(* Logix 5000 project; controller Test vendor 1 type 14 code 92 rev 33.11; software revision 33.03 *)

TASK MainTask (continuous, watchdog 500 ms) : MainProgram

MODULES
   Local : vendor 1 type 14 code 92 (ICP 0, rev 33.11)
      IN : vendor 1 type 7 code 1 (ICP 3, rev 3.2, Input RPI 20 ms)
      O : vendor 1 type 7 code 15 (ICP 2, rev 3.2, Output RPI 20 ms)
      Ethernet : 1756-ENBT (ICP 1, Ethernet 192.168.0.98, rev 6.4)
         IOLM1 : DXM (Ethernet 192.168.0.1, rev 2.22, StandardDataDriven RPI 20 ms)
              IOLM1:I.Data[184].0   // Output State
              IOLM1:I.Data[184].1   // Health Alarm State
END_MODULES

TYPE Banner_Direct_Parameters_v4 :
STRUCT
   Master_Cycle_Time : INT;
   Min_Cycle_Time : INT;
   M_Sequence_Capability : INT;
   IO_Link_Version_ID : INT;
   Process_Data_Input_Length : INT;
   Process_Data_Output_Length : INT;
   Combined_Vendor_ID : DINT;   // IO-Link Vendor ID
   Vendor_ID1 : INT;
   Vendor_ID2 : INT;
   Combined_Device_ID : DINT;   // IO-Link Device ID
   Device_ID1 : INT;
   Device_ID2 : INT;
   Device_ID3 : INT;
END_STRUCT
END_TYPE

TYPE Banner_IOL_Port_v4 :   // UDT that has all of the data items necessary to communicate with a specific Port on a IO-Link Master
STRUCT
   Port_Controlled : INT;   // Each bit represents a port on an IO-Link Master. Set to 1 to tell AOI to control that port.
   Port_Activate : INT;   // Each bit represents a port on an IO-Link Master. When ON that port will process any commands in queue.
   Port_Read : INT;   // Each bit represents a port on an IO-Link Master. Used to determine when device AOI has requested a Read command.
   Port_Write : INT;   // Each bit represents a port on an IO-Link Master. Used to determine when device AOI has requested a Write command.
   Port_RW_Complete : INT;   // Each bit represents a port on an IO-Link Master. Tells device AOI that Read or Write request has been completed.
   Port_Device_Read : INT;
   Data_Transfer : SINT[190];   // Array to transfer data from IO-Master to device AOIs.
END_STRUCT
END_TYPE

TYPE Banner_IOLM_EL_v4 :   // Error Log for Messages to IOLM.
STRUCT
   RW : SINT;   // 0 = Read, 1 = Write.
   Port : SINT;   // Port number that generated error.
   Index : INT;   // IO-Link Index for generated error.
END_STRUCT
END_TYPE

TYPE Banner_IOLM_v4 :   // UDT to control IO-Link Masters.
STRUCT
   Message_Source_Data : SINT[190];
   Message_Destination_Data : SINT[190];
   Error_Log : Banner_IOLM_EL_v4[10];
   Error_Write_Retry : BOOL;
   Num_Error_MSGS : DINT;
   IO_Link_Master_Busy : BOOL;   // 0 = While waiting for a command, 1 = Processing command
   AOI_Reset : BOOL;
   Port_Data : Banner_IOL_Port_v4;   // All of the necessary data to work with the various ports of the IO-Link Master.
   Halt_Operation : BOOL;   // When parameter is 1 the AOI is halted as next available time frame.
   AOI_Halted : BOOL;   // AOI is in standby mode until Halt Operation tag is set back to 0.
END_STRUCT
END_TYPE

TYPE Banner_S15S_TH_Alarm_Configuration_v4 :
STRUCT
   Temp_Low_Threshold : REAL;
   Temp_High_Threshold : REAL;
   Relative_Humidity_Low_Threshold : REAL;
   Relative_Humidity_High_Threshold : REAL;
   Dew_Point_Low_Threshold : REAL;
   Dew_Point_High_Threshold : REAL;
   Temp_On_Delay : REAL;
   Temp_Off_Delay : REAL;
   Relative_Humidity_On_Delay : REAL;
   Relative_Humidity_Off_Delay : REAL;
   Dew_Point_On_Delay : REAL;
   Dew_Point_Off_Delay : REAL;
END_STRUCT
END_TYPE

TYPE Banner_S15S_TH_Alarm_Counters_v4 :
STRUCT
   Temp_Low_Counter : DINT;
   Temp_High_Counter : DINT;
   Relative_Humidity_Low_Counter : DINT;
   Relative_Humidity_High_Counter : DINT;
   Dew_Point_Low_Counter : DINT;
   Dew_Point_High_Counter : DINT;
END_STRUCT
END_TYPE

TYPE Banner_S15S_TH_Floating_Point :
STRUCT
   Temp_Value : REAL;
   Temp_Over_Threshold : SINT;
   Temp_Under_Threshold : SINT;
   Dew_Point_Value : REAL;
   Dew_Point_Over_Threshold : SINT;
   Dew_Point_Under_Threshold : SINT;
   Relative_Humidity_Value : REAL;
   Relative_Humidity_Over_Threshold : SINT;
   Relative_Humidity_Under_Threshold : SINT;
END_STRUCT
END_TYPE

TYPE Banner_S15S_TH_PDI_v4 :   // Process Data for a S15S-TH-KQ. This will include event information.
STRUCT
   Smart_Fahrenheit : Banner_S15S_TH_Smart_Sensor;
   Smart_Celsius : Banner_S15S_TH_Smart_Sensor;
   Floating_Fahrenheit : Banner_S15S_TH_Floating_Point;
   Floating_Celsius : Banner_S15S_TH_Floating_Point;
   DTI : SINT[16];
END_STRUCT
END_TYPE

TYPE Banner_S15S_TH_RD_v4 :   // UDT that stores the Read Data for a S15S-TH-KQ.
STRUCT
   Direct : Banner_Direct_Parameters_v4;
   Serial_Number : STRING;
   All_Time_Run_Time : DINT;   // 0 to 2 Billion. 1/4 hr increments.
END_STRUCT
END_TYPE

TYPE Banner_S15S_TH_Smart_Sensor :
STRUCT
   Temp_Value : DINT;
   Temp_Scale : INT;
   Temp_Over_Threshold : SINT;
   Temp_Under_Threshold : SINT;
   Dew_Point_Value : DINT;
   Dew_Point_Scale : INT;
   Dew_Point_Over_Threshold : SINT;
   Dew_Point_Under_Threshold : SINT;
   Relative_Humidity_Value : DINT;
   Relative_Humidity_Scale : INT;
   Relative_Humidity_Over_Threshold : SINT;
   Relative_Humidity_Under_Threshold : SINT;
END_STRUCT
END_TYPE

TYPE Banner_S15S_TH_v4 :   // All of the parameters for a S15S-TH-KQ.
STRUCT
   Initial_Global_Read : BOOL;   // Determines if all of the IO-Link data has been read into the PLC yet
   Command : INT;   // Value placed in here will activate a read or write to a specifc IO-Link Index
   Read : Banner_S15S_TH_RD_v4;   // Read Only Data
   Write : Banner_S15S_TH_WD_v4;   // Write Data
   Reset : BOOL;   // Resets AOI. This will force a complete parameter read of the sensor.
END_STRUCT
END_TYPE

TYPE Banner_S15S_TH_WD_v4 :   // UDT that stores the Write Data for a S15S-TH-KQ.
STRUCT
   System_Command : INT;   // See IODD file for list of commands that can be activated via the System Command interface
   Parameter_Access_Lock : SINT;   // Write access to all parameters is prohibited while value is 1. Only this parameter can be adjusted when value is 1.
   Data_Storage_Lock : SINT;   // Automatic data storage is disabled when this value is equal to 1. Read access is not affected.
   Local_Parameterization_Lock : SINT;   // Parameterization via local control elements on device is disabled.
   Local_User_Interface_Lock : SINT;   // Operation of local user interface is disabled.
   Resettable_Run_Time_Counter : DINT;   // 0 to 2 Billion. 1/4 hr increments.
   Alarm_Config : Banner_S15S_TH_Alarm_Configuration_v4;
   Alarm_Counters : Banner_S15S_TH_Alarm_Counters_v4;
   Process_Data_Mode : INT;   // 1=Smart Sensor Profile, Fahrenheit, 2=Smart Sensor Profile, Celsius, 3=Floating Point, Fahrenheit, 4=Floating Point, Celsius
   Output_Config : INT;   // 0=BannerBus,1=Discrete Output
END_STRUCT
END_TYPE

ADD_ON_INSTRUCTION Banner_DXMR_IOLM_Param_v4   (* revision 4.3, vendor Banner Engineering *)
// AOI that controls a Banner IO-Link Master with Banner devices for parameter data operations.
// Revision note:
// Updated name of AOI.
VAR_IN_OUT
   IOLM : Banner_IOLM_v4; {required}
END_VAR
VAR
   Lock : DINT; {access None}
   Byte_Length : SINT; {access None}
   Current_Port : INT; {access None}   // Current port to communicate with via the IO-Link Master.
   Timer1 : TIMER := (PRE := 500); {access None}
   Error_Index : DINT; {access None}
   Timer2 : TIMER := (PRE := 5000); {access None}
   Temp_Index : INT; {access None}
   ErrCount : DINT; {access None}
   Timer4 : TIMER := (PRE := 2000); {access None}
   Timer5 : TIMER := (PRE := 2000); {access None}
   Timer3 : TIMER := (PRE := 2000); {access None}
   Timer6 : TIMER := (PRE := 3000); {access None}
   Timer7 : TIMER := (PRE := 3000); {access None}
   Timer8 : TIMER := (PRE := 3000); {access None}
END_VAR

ROUTINE Logic   (* ladder *)
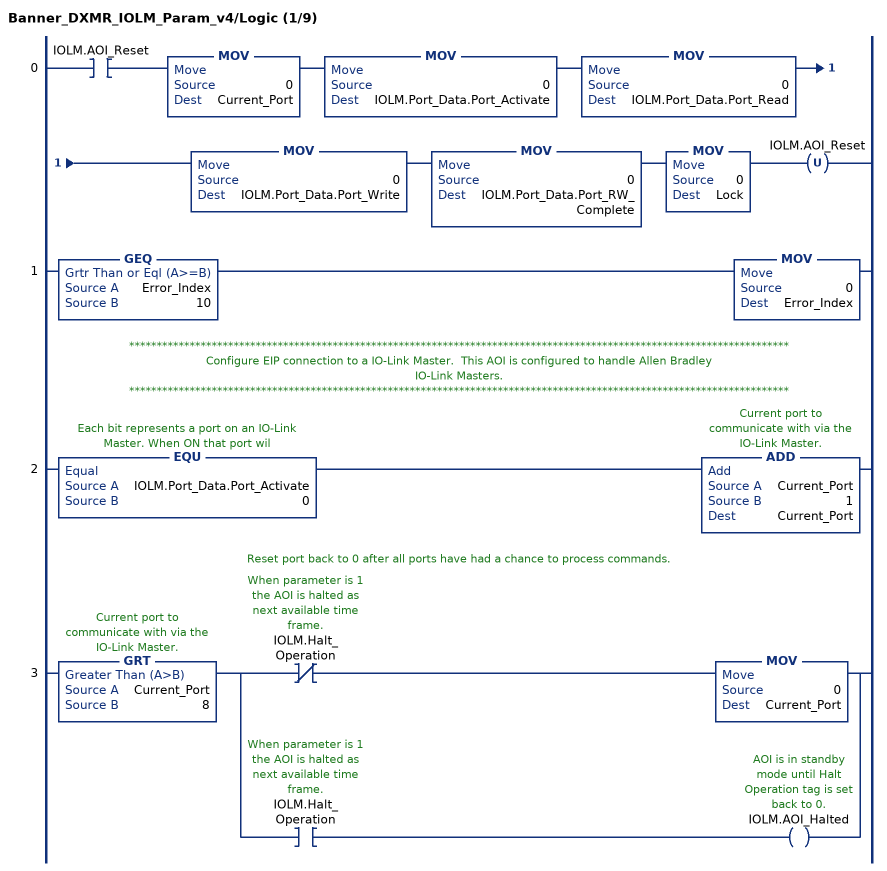
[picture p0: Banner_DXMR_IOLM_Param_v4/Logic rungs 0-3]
   0: XIC(IOLM.AOI_Reset)MOV(0,Current_Port)MOV(0,IOLM.Port_Data.Port_Activate)MOV(0,IOLM.Port_Data.Port_Read)MOV(0,IOLM.Port_Data.Port_Write)MOV(0,IOLM.Port_Data.Port_RW_Complete)MOV(0,Lock)OTU(IOLM.AOI_Reset);
   1: GEQ(Error_Index,10)MOV(0,Error_Index);
   // ************************************************************************************************************************
   // Configure EIP connection to a IO-Link Master.  This AOI is configured to handle Allen Bradley
   // IO-Link Masters.
   // ************************************************************************************************************************
   2: EQU(IOLM.Port_Data.Port_Activate,0)ADD(Current_Port,1,Current_Port);
   // Reset port back to 0 after all ports have had a chance to process commands.
   3: GRT(Current_Port,8)[XIO(IOLM.Halt_Operation) MOV(0,Current_Port) ,XIC(IOLM.Halt_Operation) OTE(IOLM.AOI_Halted) ];
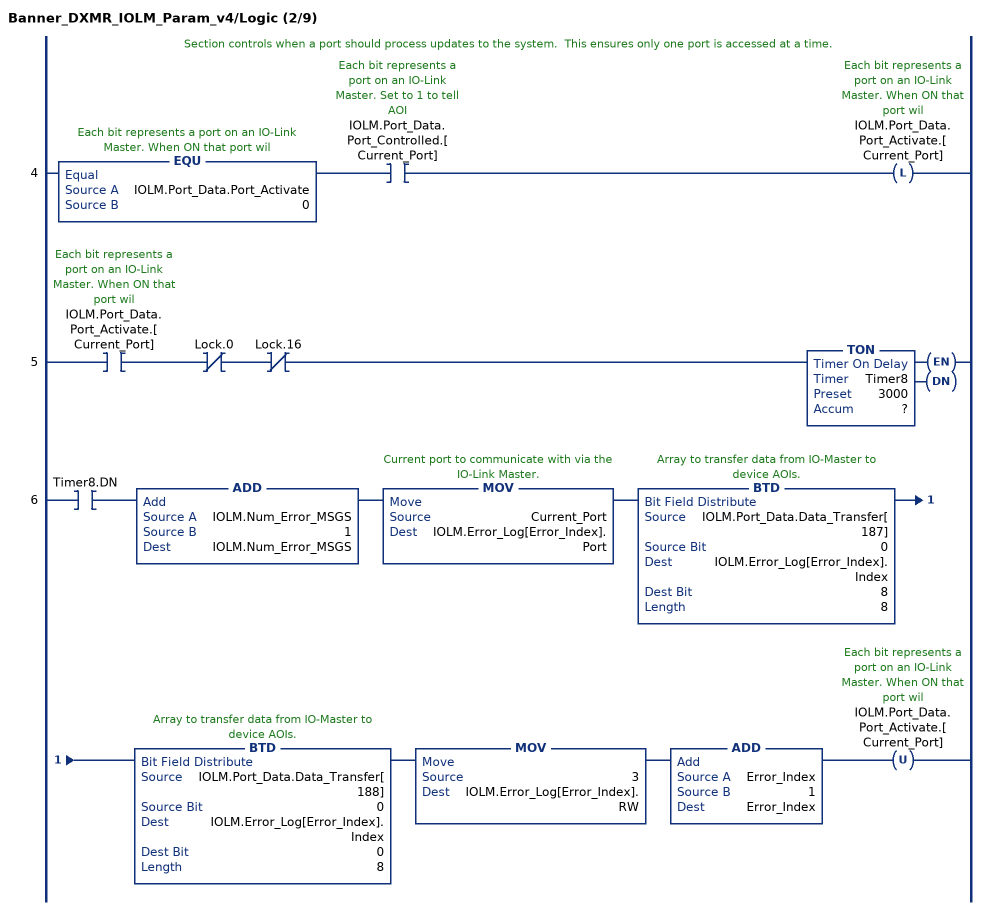
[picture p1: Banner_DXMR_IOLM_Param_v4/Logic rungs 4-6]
   // Section controls when a port should process updates to the system.  This ensures only one port is accessed at a time.
   4: EQU(IOLM.Port_Data.Port_Activate,0)XIC(IOLM.Port_Data.Port_Controlled.[Current_Port])OTL(IOLM.Port_Data.Port_Activate.[Current_Port]);
   5: XIC(IOLM.Port_Data.Port_Activate.[Current_Port])XIO(Lock.0)XIO(Lock.16)TON(Timer8,?,?);
   6: XIC(Timer8.DN)ADD(IOLM.Num_Error_MSGS,1,IOLM.Num_Error_MSGS)MOV(Current_Port,IOLM.Error_Log[Error_Index].Port)BTD(IOLM.Port_Data.Data_Transfer[187],0,IOLM.Error_Log[Error_Index].Index,8,8)BTD(IOLM.Port_Data.Data_Transfer[188],0,IOLM.Error_Log[Error_Index].Index,0,8)MOV(3,IOLM.Error_Log[Error_Index].RW)ADD(Error_Index,1,Error_Index)OTU(IOLM.Port_Data.Port_Activate.[Current_Port]);
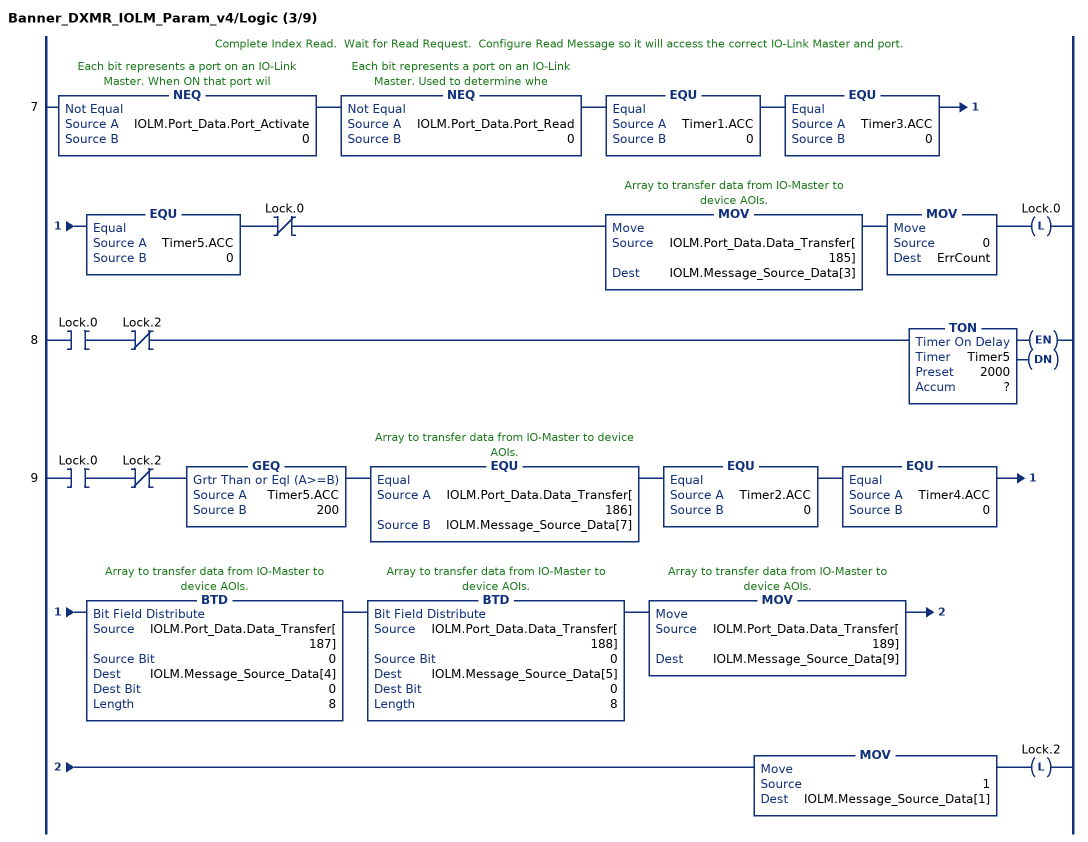
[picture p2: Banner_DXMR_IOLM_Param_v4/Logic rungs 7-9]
   // Complete Index Read.  Wait for Read Request.  Configure Read Message so it will access the correct IO-Link Master and port.
   7: NEQ(IOLM.Port_Data.Port_Activate,0)NEQ(IOLM.Port_Data.Port_Read,0)EQU(Timer1.ACC,0)EQU(Timer3.ACC,0)EQU(Timer5.ACC,0)XIO(Lock.0)MOV(IOLM.Port_Data.Data_Transfer[185],IOLM.Message_Source_Data[3])MOV(0,ErrCount)OTL(Lock.0);
   8: XIC(Lock.0)XIO(Lock.2)TON(Timer5,?,?);
   9: XIC(Lock.0)XIO(Lock.2)GEQ(Timer5.ACC,200)EQU(IOLM.Port_Data.Data_Transfer[186],IOLM.Message_Source_Data[7])EQU(Timer2.ACC,0)EQU(Timer4.ACC,0)BTD(IOLM.Port_Data.Data_Transfer[187],0,IOLM.Message_Source_Data[4],0,8)BTD(IOLM.Port_Data.Data_Transfer[188],0,IOLM.Message_Source_Data[5],0,8)MOV(IOLM.Port_Data.Data_Transfer[189],IOLM.Message_Source_Data[9])MOV(1,IOLM.Message_Source_Data[1])OTL(Lock.2);
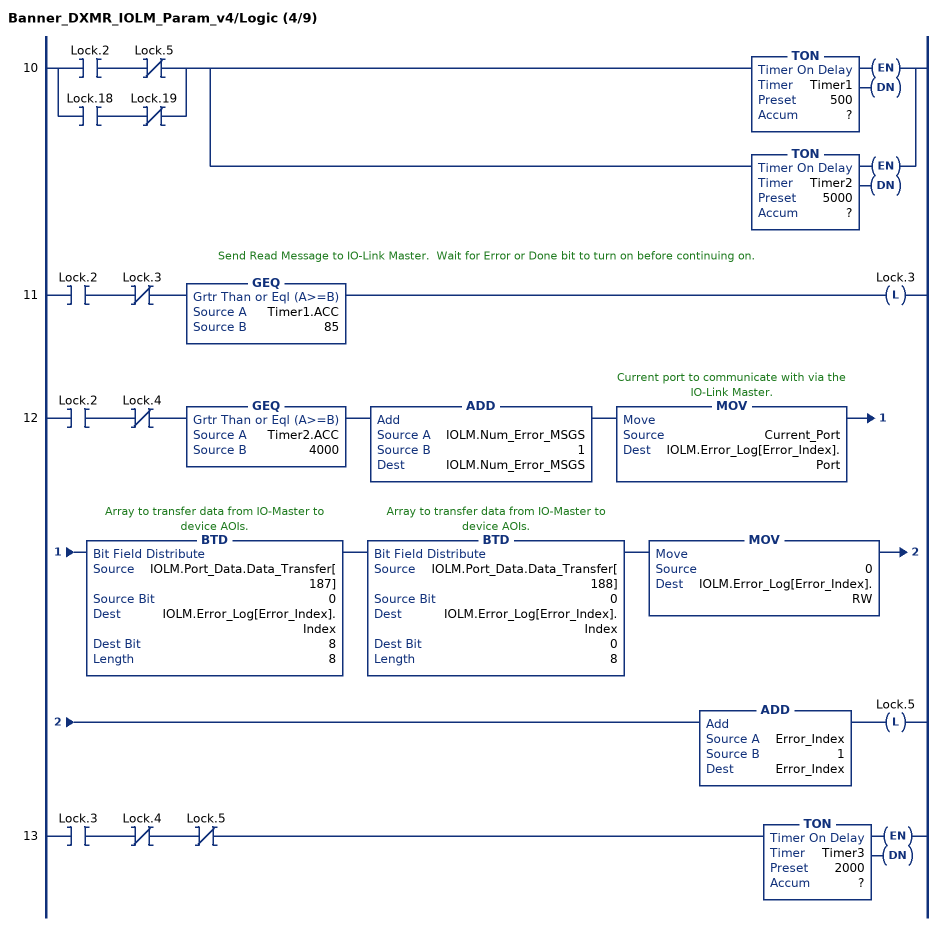
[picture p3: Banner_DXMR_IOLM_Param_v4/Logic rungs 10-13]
   10: [XIC(Lock.2) XIO(Lock.5) ,XIC(Lock.18) XIO(Lock.19) ][TON(Timer1,?,?) ,TON(Timer2,?,?) ];
   // Send Read Message to IO-Link Master.  Wait for Error or Done bit to turn on before continuing on.
   11: XIC(Lock.2)XIO(Lock.3)GEQ(Timer1.ACC,85)OTL(Lock.3);
   12: XIC(Lock.2)XIO(Lock.4)GEQ(Timer2.ACC,4000)ADD(IOLM.Num_Error_MSGS,1,IOLM.Num_Error_MSGS)MOV(Current_Port,IOLM.Error_Log[Error_Index].Port)BTD(IOLM.Port_Data.Data_Transfer[187],0,IOLM.Error_Log[Error_Index].Index,8,8)BTD(IOLM.Port_Data.Data_Transfer[188],0,IOLM.Error_Log[Error_Index].Index,0,8)MOV(0,IOLM.Error_Log[Error_Index].RW)ADD(Error_Index,1,Error_Index)OTL(Lock.5);
   13: XIC(Lock.3)XIO(Lock.4)XIO(Lock.5)TON(Timer3,?,?);
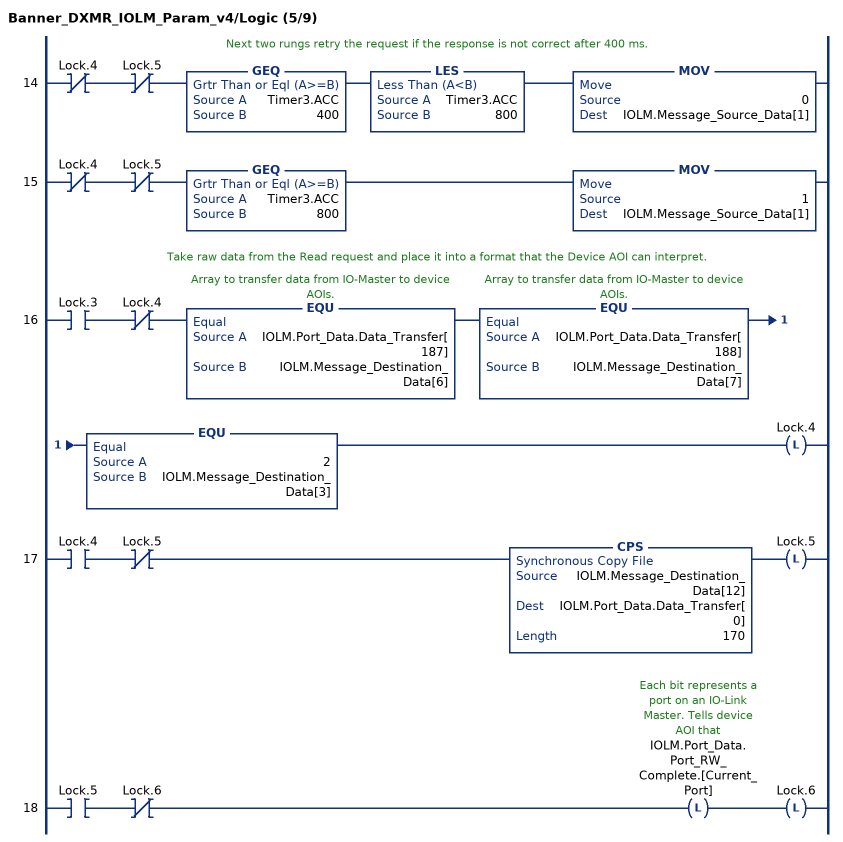
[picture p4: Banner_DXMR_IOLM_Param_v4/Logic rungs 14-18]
   // Next two rungs retry the request if the response is not correct after 400 ms.
   14: XIO(Lock.4)XIO(Lock.5)GEQ(Timer3.ACC,400)LES(Timer3.ACC,800)MOV(0,IOLM.Message_Source_Data[1]);
   15: XIO(Lock.4)XIO(Lock.5)GEQ(Timer3.ACC,800)MOV(1,IOLM.Message_Source_Data[1]);
   // Take raw data from the Read request and place it into a format that the Device AOI can interpret.
   16: XIC(Lock.3)XIO(Lock.4)EQU(IOLM.Port_Data.Data_Transfer[187],IOLM.Message_Destination_Data[6])EQU(IOLM.Port_Data.Data_Transfer[188],IOLM.Message_Destination_Data[7])EQU(2,IOLM.Message_Destination_Data[3])OTL(Lock.4);
   17: XIC(Lock.4)XIO(Lock.5)CPS(IOLM.Message_Destination_Data[12],IOLM.Port_Data.Data_Transfer[0],170)OTL(Lock.5);
   18: XIC(Lock.5)XIO(Lock.6)OTL(IOLM.Port_Data.Port_RW_Complete.[Current_Port])OTL(Lock.6);
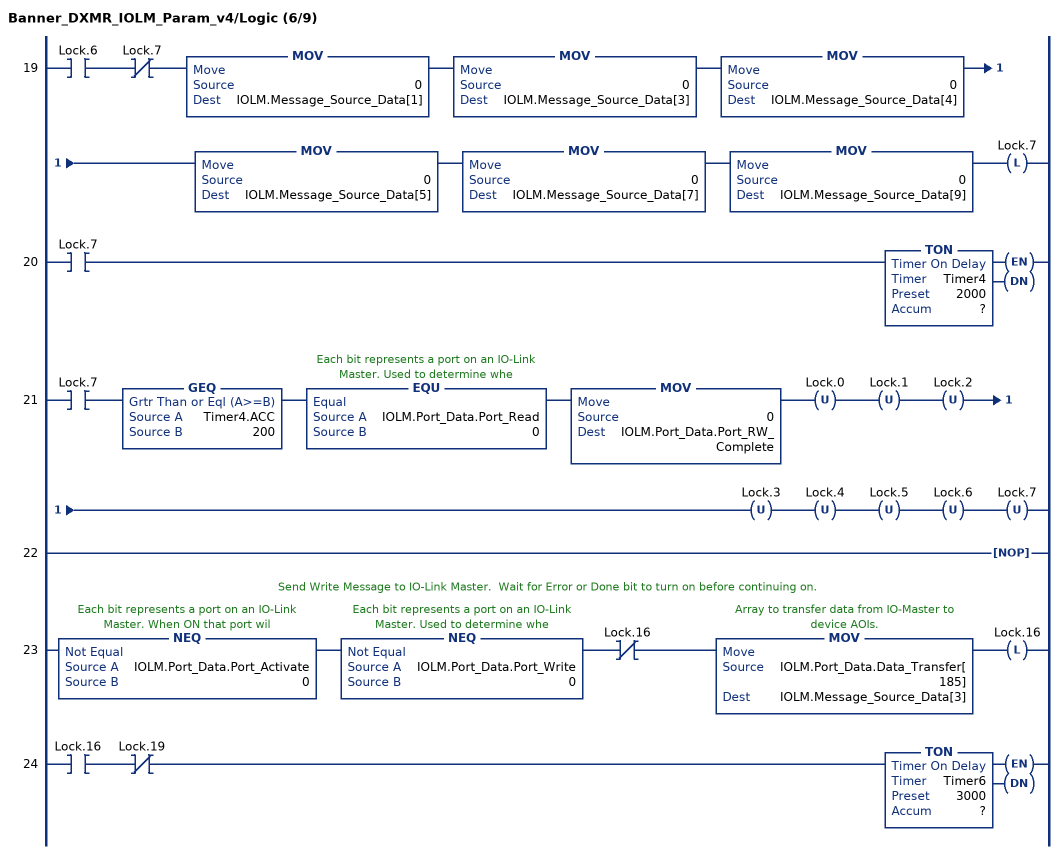
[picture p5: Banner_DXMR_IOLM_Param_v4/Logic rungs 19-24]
   19: XIC(Lock.6)XIO(Lock.7)MOV(0,IOLM.Message_Source_Data[1])MOV(0,IOLM.Message_Source_Data[3])MOV(0,IOLM.Message_Source_Data[4])MOV(0,IOLM.Message_Source_Data[5])MOV(0,IOLM.Message_Source_Data[7])MOV(0,IOLM.Message_Source_Data[9])OTL(Lock.7);
   20: XIC(Lock.7)TON(Timer4,?,?);
   21: XIC(Lock.7)GEQ(Timer4.ACC,200)EQU(IOLM.Port_Data.Port_Read,0)MOV(0,IOLM.Port_Data.Port_RW_Complete)OTU(Lock.0)OTU(Lock.1)OTU(Lock.2)OTU(Lock.3)OTU(Lock.4)OTU(Lock.5)OTU(Lock.6)OTU(Lock.7);
   22: NOP();
   // Send Write Message to IO-Link Master.  Wait for Error or Done bit to turn on before continuing on.
   23: NEQ(IOLM.Port_Data.Port_Activate,0)NEQ(IOLM.Port_Data.Port_Write,0)XIO(Lock.16)MOV(IOLM.Port_Data.Data_Transfer[185],IOLM.Message_Source_Data[3])OTL(Lock.16);
   24: XIC(Lock.16)XIO(Lock.19)TON(Timer6,?,?);
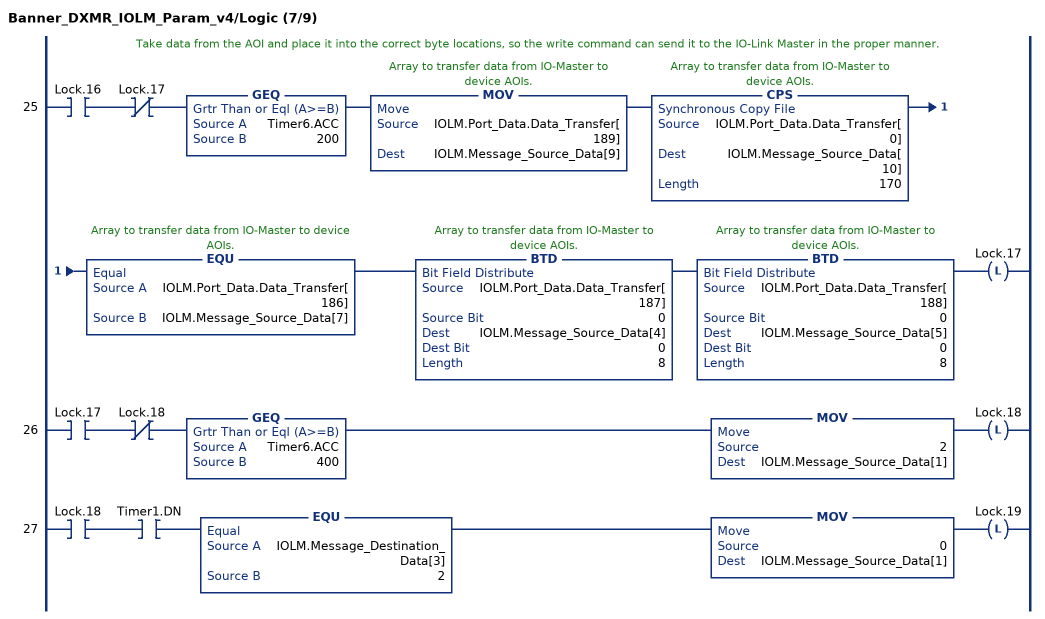
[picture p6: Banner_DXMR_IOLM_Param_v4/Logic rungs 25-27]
   // Take data from the AOI and place it into the correct byte locations, so the write command can send it to the IO-Link Master in the proper manner.
   25: XIC(Lock.16)XIO(Lock.17)GEQ(Timer6.ACC,200)MOV(IOLM.Port_Data.Data_Transfer[189],IOLM.Message_Source_Data[9])CPS(IOLM.Port_Data.Data_Transfer[0],IOLM.Message_Source_Data[10],170)EQU(IOLM.Port_Data.Data_Transfer[186],IOLM.Message_Source_Data[7])BTD(IOLM.Port_Data.Data_Transfer[187],0,IOLM.Message_Source_Data[4],0,8)BTD(IOLM.Port_Data.Data_Transfer[188],0,IOLM.Message_Source_Data[5],0,8)OTL(Lock.17);
   26: XIC(Lock.17)XIO(Lock.18)GEQ(Timer6.ACC,400)MOV(2,IOLM.Message_Source_Data[1])OTL(Lock.18);
   27: XIC(Lock.18)XIC(Timer1.DN)EQU(IOLM.Message_Destination_Data[3],2)MOV(0,IOLM.Message_Source_Data[1])OTL(Lock.19);
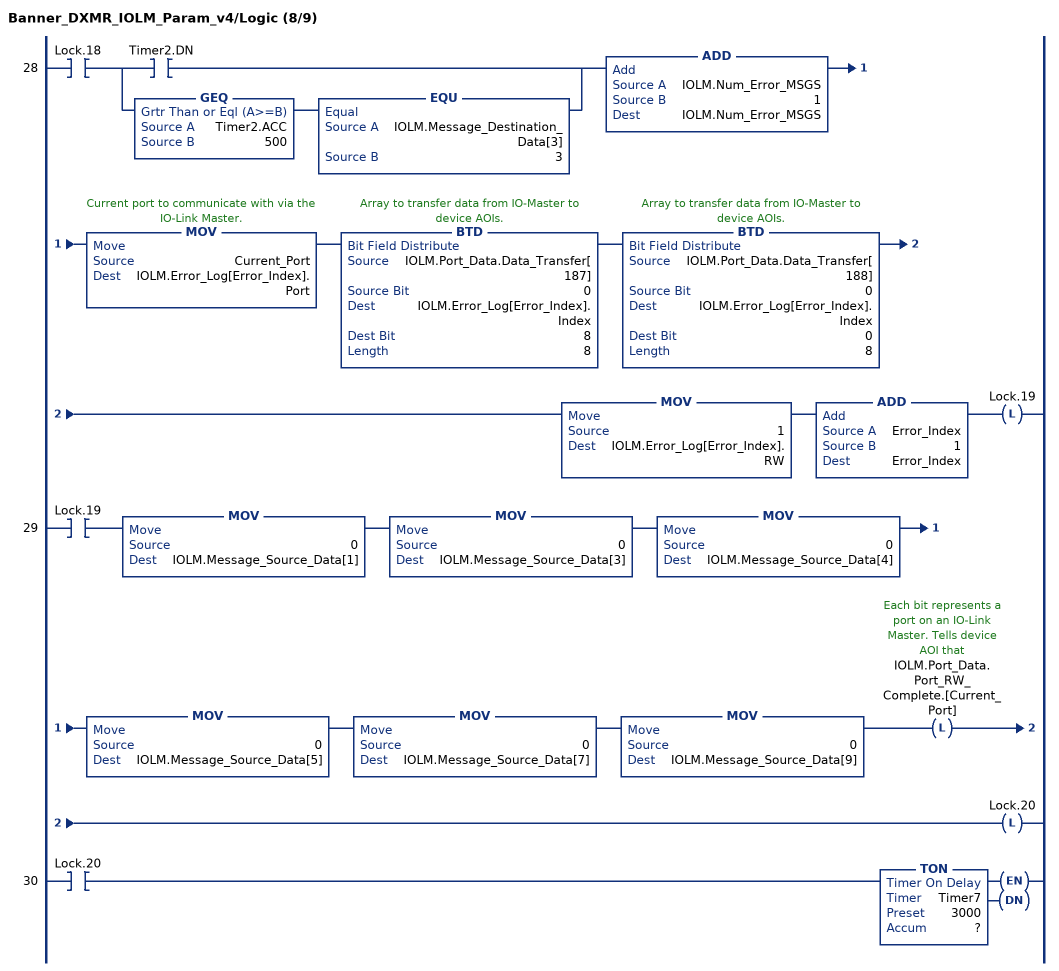
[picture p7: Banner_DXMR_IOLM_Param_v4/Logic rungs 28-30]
   28: XIC(Lock.18)[XIC(Timer2.DN) ,GEQ(Timer2.ACC,500) EQU(IOLM.Message_Destination_Data[3],3) ]ADD(IOLM.Num_Error_MSGS,1,IOLM.Num_Error_MSGS)MOV(Current_Port,IOLM.Error_Log[Error_Index].Port)BTD(IOLM.Port_Data.Data_Transfer[187],0,IOLM.Error_Log[Error_Index].Index,8,8)BTD(IOLM.Port_Data.Data_Transfer[188],0,IOLM.Error_Log[Error_Index].Index,0,8)MOV(1,IOLM.Error_Log[Error_Index].RW)ADD(Error_Index,1,Error_Index)OTL(Lock.19);
   29: XIC(Lock.19)MOV(0,IOLM.Message_Source_Data[1])MOV(0,IOLM.Message_Source_Data[3])MOV(0,IOLM.Message_Source_Data[4])MOV(0,IOLM.Message_Source_Data[5])MOV(0,IOLM.Message_Source_Data[7])MOV(0,IOLM.Message_Source_Data[9])OTL(IOLM.Port_Data.Port_RW_Complete.[Current_Port])OTL(Lock.20);
   30: XIC(Lock.20)TON(Timer7,?,?);
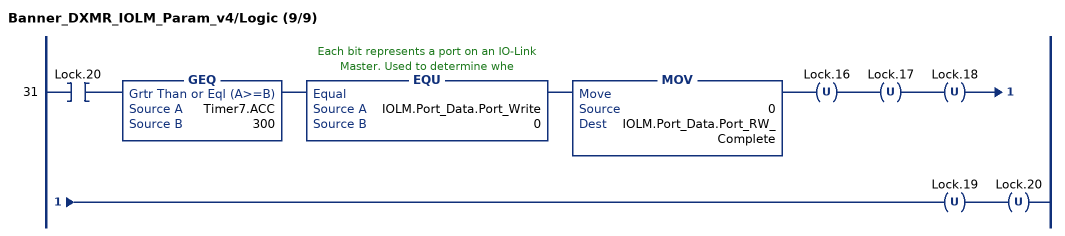
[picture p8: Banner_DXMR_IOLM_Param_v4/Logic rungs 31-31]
   31: XIC(Lock.20)GEQ(Timer7.ACC,300)EQU(IOLM.Port_Data.Port_Write,0)MOV(0,IOLM.Port_Data.Port_RW_Complete)OTU(Lock.16)OTU(Lock.17)OTU(Lock.18)OTU(Lock.19)OTU(Lock.20);
END_ROUTINE
END_ADD_ON_INSTRUCTION

ADD_ON_INSTRUCTION Banner_S15S_TH_Float_In_v4   (* revision 4.0 *)
// AOI the orientates the bytes for a floating point value.
VAR_IN_OUT
   Float : REAL; {required}
END_VAR
VAR_INPUT
   Sint0 : SINT; {required}
   Sint1 : SINT; {required}
   Sint2 : SINT; {required}
   Sint3 : SINT; {required}
END_VAR
VAR
   Temp_Byte : SINT[4]; {access None}
END_VAR

ROUTINE Logic   (* ladder *)
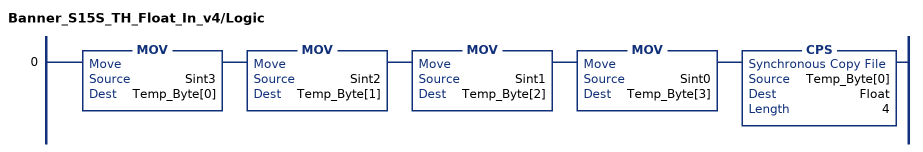
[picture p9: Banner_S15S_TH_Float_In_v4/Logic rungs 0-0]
   0: MOV(Sint3,Temp_Byte[0])MOV(Sint2,Temp_Byte[1])MOV(Sint1,Temp_Byte[2])MOV(Sint0,Temp_Byte[3])CPS(Temp_Byte[0],Float,4);
END_ROUTINE
END_ADD_ON_INSTRUCTION

ADD_ON_INSTRUCTION Banner_S15S_TH_Float_Out_v4   (* revision 4.0 *)
// AOI the orientates the bytes for a floating point value.
VAR_INPUT
   Float : REAL; {required}
END_VAR
VAR_IN_OUT
   Sint0 : SINT; {required}
   Sint1 : SINT; {required}
   Sint2 : SINT; {required}
   Sint3 : SINT; {required}
END_VAR
VAR
   Temp_Byte : SINT[4]; {access None}
END_VAR

ROUTINE Logic   (* ladder *)
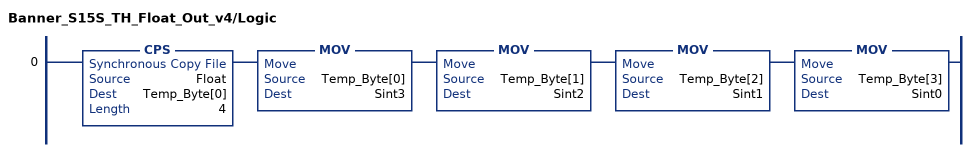
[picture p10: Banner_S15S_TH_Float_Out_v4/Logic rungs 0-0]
   0: CPS(Float,Temp_Byte[0],4)MOV(Temp_Byte[0],Sint3)MOV(Temp_Byte[1],Sint2)MOV(Temp_Byte[2],Sint1)MOV(Temp_Byte[3],Sint0);
END_ROUTINE
END_ADD_ON_INSTRUCTION

ADD_ON_INSTRUCTION Banner_S15S_TH_Param_v4   (* revision 4.0, vendor Banner Engineering *)
// AOI to read and write parameter data to an IO-Link S15S-TH-KQ.
VAR_IN_OUT
   S15STH : Banner_S15S_TH_v4; {required}
   Port_Data : Banner_IOL_Port_v4; {required}
END_VAR
VAR_INPUT
   Port : DINT; {required}
END_VAR
VAR
   Local_Control : DINT; {access None}
   Global_Read_Command_Value : INT; {access None}
   Global_Write_Command_Value : INT; {access None}
   Command_Being_Processed : BOOL; {access None}
   Update_Archive : BOOL; {access None}
   Index_Write_Inprocess : INT; {access None}
   Index_Write_Control : INT; {access None}
   Inprocess_Index : DINT; {access None}
   AOI_Out_Status : Banner_S15S_TH_Float_Out_v4[12]; {access None}
   AOI_In_Status : Banner_S15S_TH_Float_In_v4[12]; {access None}
END_VAR

ROUTINE Logic   (* ladder *)
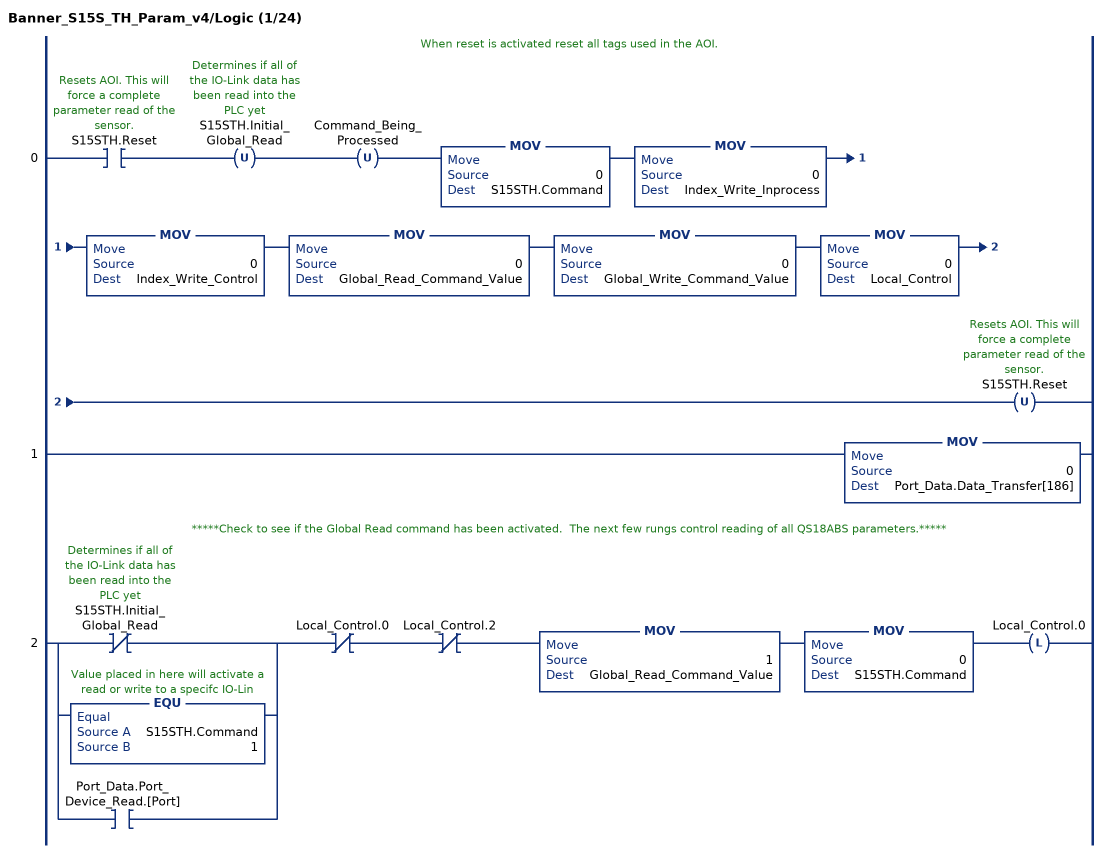
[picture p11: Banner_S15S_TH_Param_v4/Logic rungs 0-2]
   // When reset is activated reset all tags used in the AOI.
   0: XIC(S15STH.Reset)OTU(S15STH.Initial_Global_Read)OTU(Command_Being_Processed)MOV(0,S15STH.Command)MOV(0,Index_Write_Inprocess)MOV(0,Index_Write_Control)MOV(0,Global_Read_Command_Value)MOV(0,Global_Write_Command_Value)MOV(0,Local_Control)OTU(S15STH.Reset);
   1: MOV(0,Port_Data.Data_Transfer[186]);
   // *****Check to see if the Global Read command has been activated.  The next few rungs control reading of all QS18ABS parameters.*****
   2: [XIO(S15STH.Initial_Global_Read) ,EQU(S15STH.Command,1) ,XIC(Port_Data.Port_Device_Read.[Port]) ]XIO(Local_Control.0)XIO(Local_Control.2)MOV(1,Global_Read_Command_Value)MOV(0,S15STH.Command)OTL(Local_Control.0);
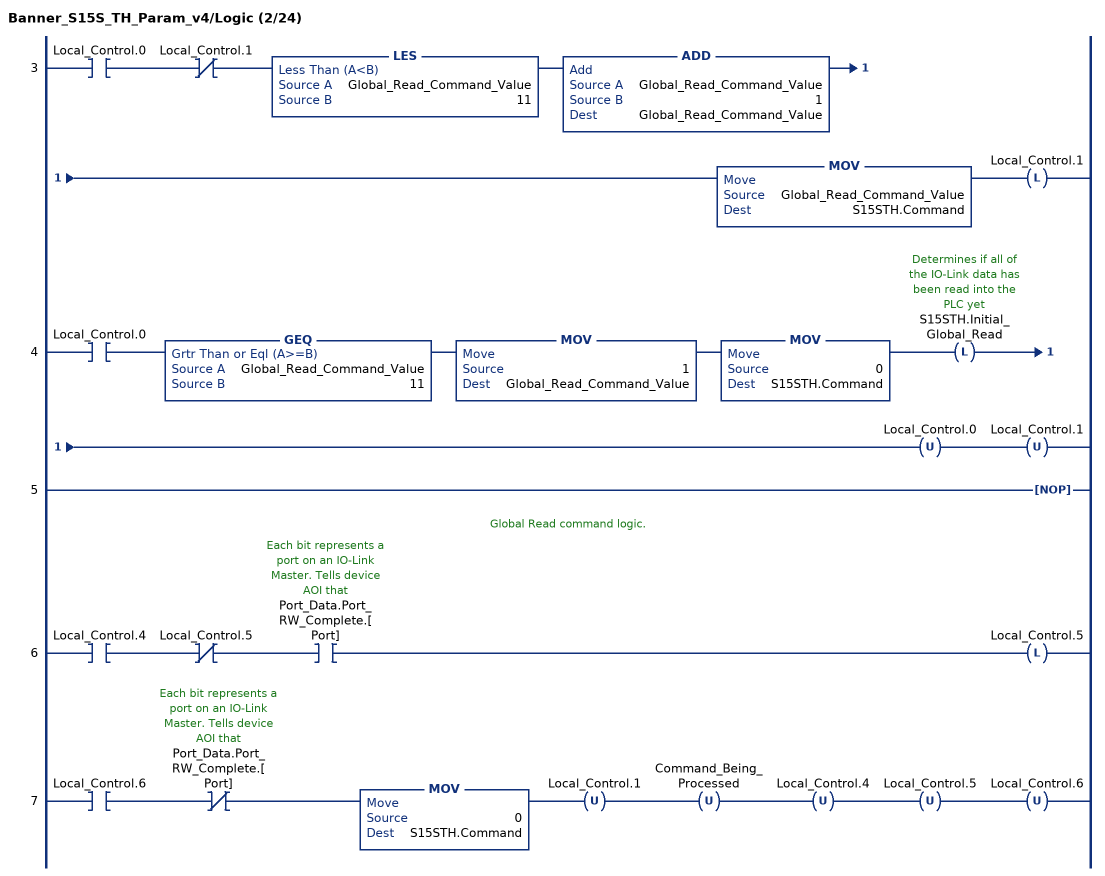
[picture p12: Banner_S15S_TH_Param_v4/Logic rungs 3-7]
   3: XIC(Local_Control.0)XIO(Local_Control.1)LES(Global_Read_Command_Value,11)ADD(Global_Read_Command_Value,1,Global_Read_Command_Value)MOV(Global_Read_Command_Value,S15STH.Command)OTL(Local_Control.1);
   4: XIC(Local_Control.0)GEQ(Global_Read_Command_Value,11)MOV(1,Global_Read_Command_Value)MOV(0,S15STH.Command)OTL(S15STH.Initial_Global_Read)OTU(Local_Control.0)OTU(Local_Control.1);
   5: NOP();
   // Global Read command logic.
   6: XIC(Local_Control.4)XIO(Local_Control.5)XIC(Port_Data.Port_RW_Complete.[Port])OTL(Local_Control.5);
   7: XIC(Local_Control.6)XIO(Port_Data.Port_RW_Complete.[Port])MOV(0,S15STH.Command)OTU(Local_Control.1)OTU(Command_Being_Processed)OTU(Local_Control.4)OTU(Local_Control.5)OTU(Local_Control.6);
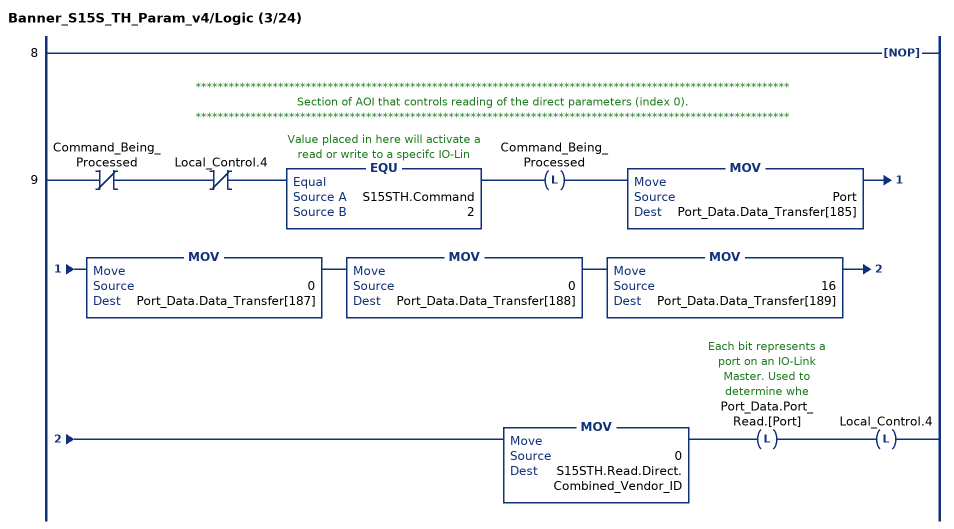
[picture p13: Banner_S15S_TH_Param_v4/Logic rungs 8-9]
   8: NOP();
   // ************************************************************************************************************
   // Section of AOI that controls reading of the direct parameters (index 0).
   // ************************************************************************************************************
   9: XIO(Command_Being_Processed)XIO(Local_Control.4)EQU(S15STH.Command,2)OTL(Command_Being_Processed)MOV(Port,Port_Data.Data_Transfer[185])MOV(0,Port_Data.Data_Transfer[187])MOV(0,Port_Data.Data_Transfer[188])MOV(16,Port_Data.Data_Transfer[189])MOV(0,S15STH.Read.Direct.Combined_Vendor_ID)OTL(Port_Data.Port_Read.[Port])OTL(Local_Control.4);
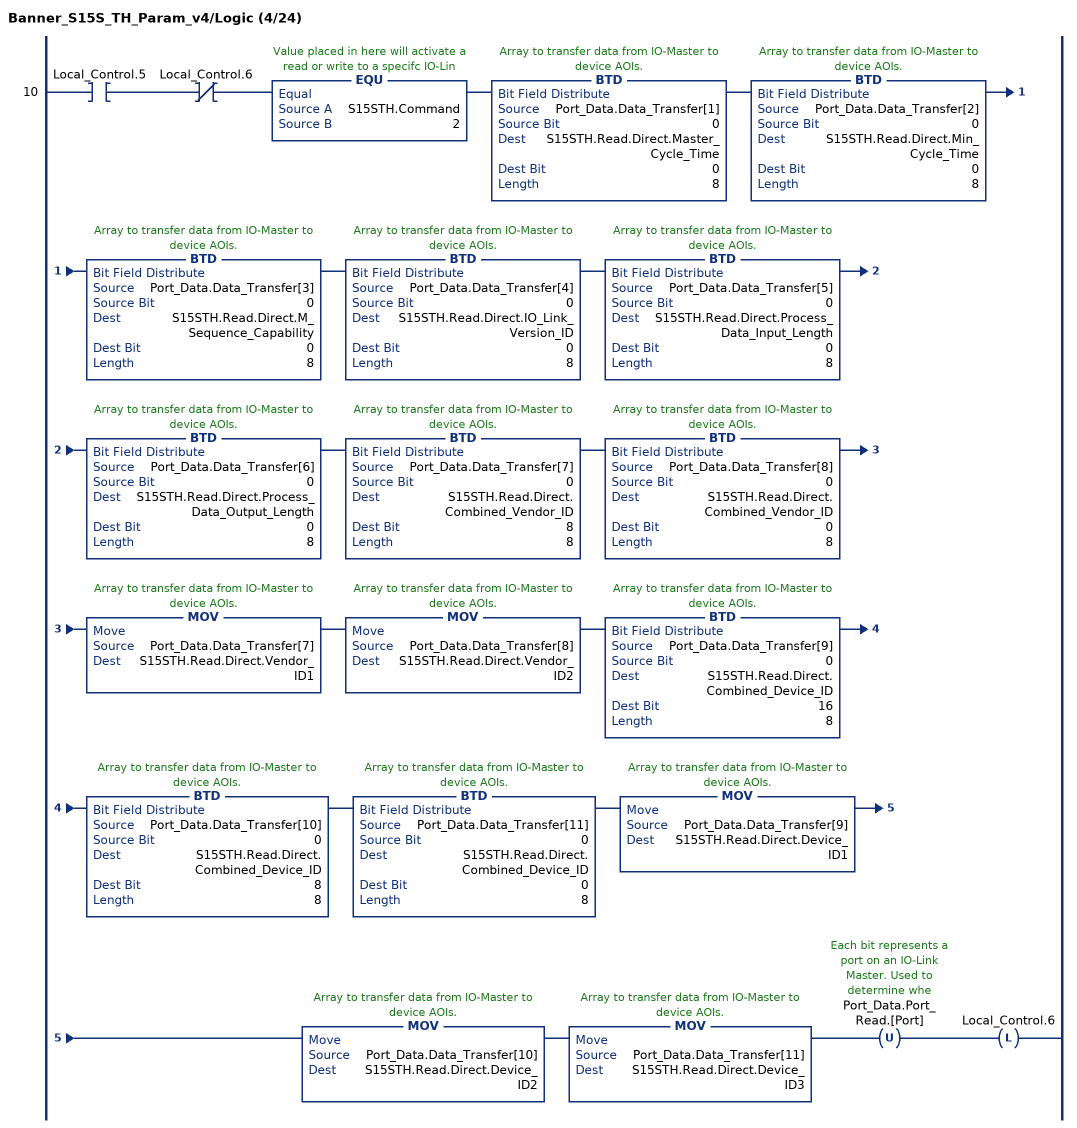
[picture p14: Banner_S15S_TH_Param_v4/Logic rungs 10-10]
   10: XIC(Local_Control.5)XIO(Local_Control.6)EQU(S15STH.Command,2)BTD(Port_Data.Data_Transfer[1],0,S15STH.Read.Direct.Master_Cycle_Time,0,8)BTD(Port_Data.Data_Transfer[2],0,S15STH.Read.Direct.Min_Cycle_Time,0,8)BTD(Port_Data.Data_Transfer[3],0,S15STH.Read.Direct.M_Sequence_Capability,0,8)BTD(Port_Data.Data_Transfer[4],0,S15STH.Read.Direct.IO_Link_Version_ID,0,8)BTD(Port_Data.Data_Transfer[5],0,S15STH.Read.Direct.Process_Data_Input_Length,0,8)BTD(Port_Data.Data_Transfer[6],0,S15STH.Read.Direct.Process_Data_Output_Length,0,8)BTD(Port_Data.Data_Transfer[7],0,S15STH.Read.Direct.Combined_Vendor_ID,8,8)BTD(Port_Data.Data_Transfer[8],0,S15STH.Read.Direct.Combined_Vendor_ID,0,8)MOV(Port_Data.Data_Transfer[7],S15STH.Read.Direct.Vendor_ID1)MOV(Port_Data.Data_Transfer[8],S15STH.Read.Direct.Vendor_ID2)BTD(Port_Data.Data_Transfer[9],0,S15STH.Read.Direct.Combined_Device_ID,16,8)BTD(Port_Data.Data_Transfer[10],0,S15STH.Read.Direct.Combined_Device_ID,8,8)BTD(Port_Data.Data_Transfer[11],0,S15STH.Read.Direct.Combined_Device_ID,0,8)MOV(Port_Data.Data_Transfer[9],S15STH.Read.Direct.Device_ID1)MOV(Port_Data.Data_Transfer[10],S15STH.Read.Direct.Device_ID2)MOV(Port_Data.Data_Transfer[11],S15STH.Read.Direct.Device_ID3)OTU(Port_Data.Port_Read.[Port])OTL(Local_Control.6);
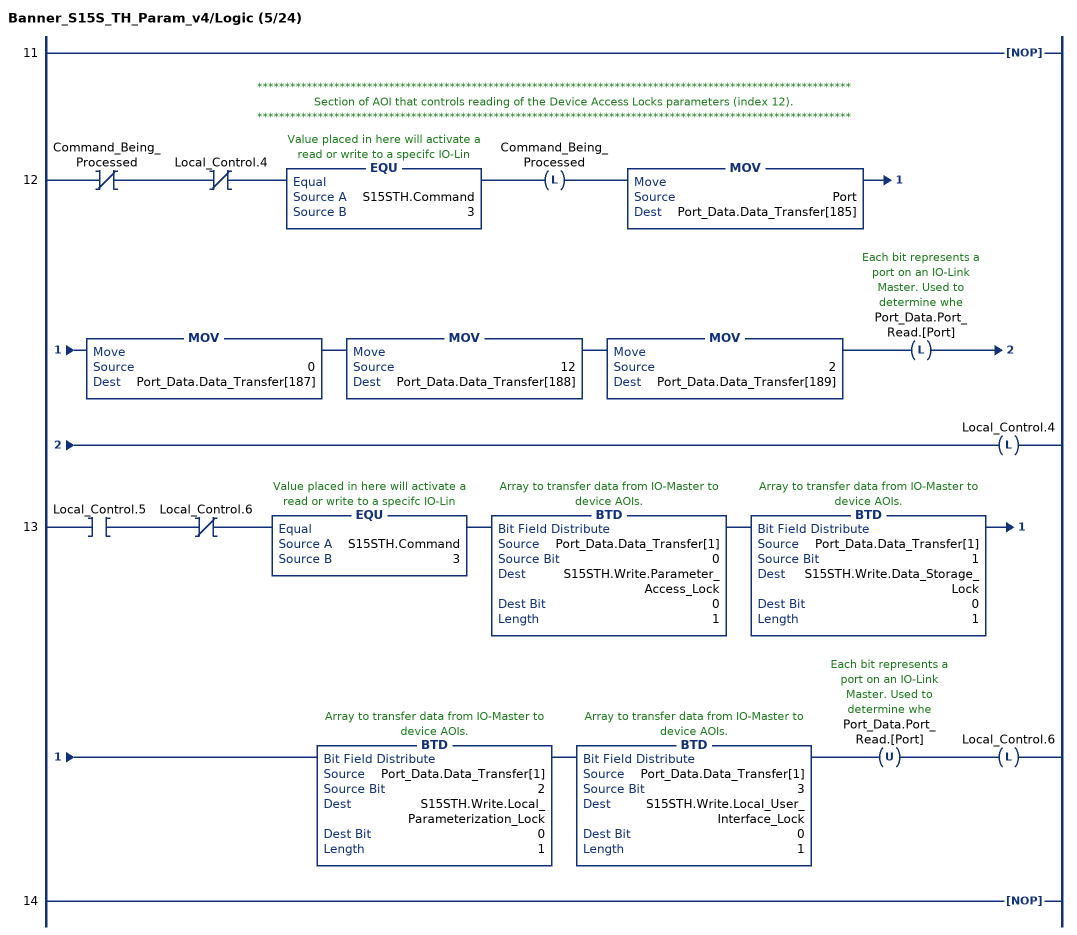
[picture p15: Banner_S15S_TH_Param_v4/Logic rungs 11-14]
   11: NOP();
   // ************************************************************************************************************
   // Section of AOI that controls reading of the Device Access Locks parameters (index 12).
   // ************************************************************************************************************
   12: XIO(Command_Being_Processed)XIO(Local_Control.4)EQU(S15STH.Command,3)OTL(Command_Being_Processed)MOV(Port,Port_Data.Data_Transfer[185])MOV(0,Port_Data.Data_Transfer[187])MOV(12,Port_Data.Data_Transfer[188])MOV(2,Port_Data.Data_Transfer[189])OTL(Port_Data.Port_Read.[Port])OTL(Local_Control.4);
   13: XIC(Local_Control.5)XIO(Local_Control.6)EQU(S15STH.Command,3)BTD(Port_Data.Data_Transfer[1],0,S15STH.Write.Parameter_Access_Lock,0,1)BTD(Port_Data.Data_Transfer[1],1,S15STH.Write.Data_Storage_Lock,0,1)BTD(Port_Data.Data_Transfer[1],2,S15STH.Write.Local_Parameterization_Lock,0,1)BTD(Port_Data.Data_Transfer[1],3,S15STH.Write.Local_User_Interface_Lock,0,1)OTU(Port_Data.Port_Read.[Port])OTL(Local_Control.6);
   14: NOP();
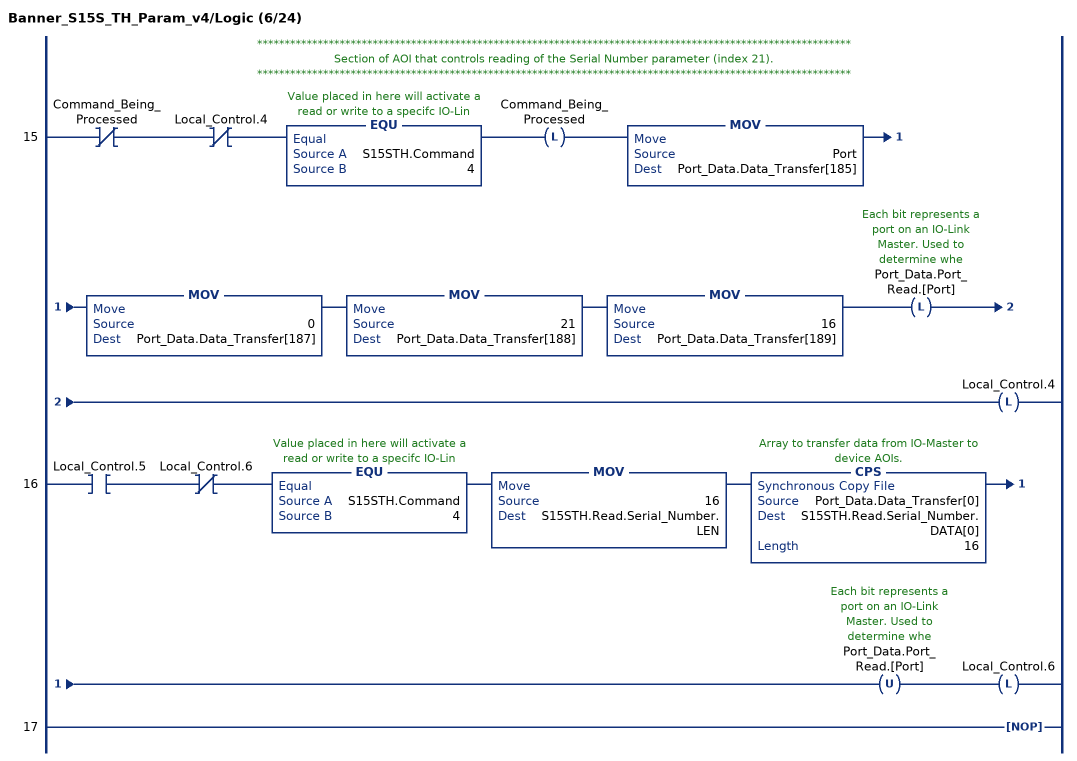
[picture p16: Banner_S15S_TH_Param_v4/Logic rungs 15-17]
   // ************************************************************************************************************
   // Section of AOI that controls reading of the Serial Number parameter (index 21).
   // ************************************************************************************************************
   15: XIO(Command_Being_Processed)XIO(Local_Control.4)EQU(S15STH.Command,4)OTL(Command_Being_Processed)MOV(Port,Port_Data.Data_Transfer[185])MOV(0,Port_Data.Data_Transfer[187])MOV(21,Port_Data.Data_Transfer[188])MOV(16,Port_Data.Data_Transfer[189])OTL(Port_Data.Port_Read.[Port])OTL(Local_Control.4);
   16: XIC(Local_Control.5)XIO(Local_Control.6)EQU(S15STH.Command,4)MOV(16,S15STH.Read.Serial_Number.LEN)CPS(Port_Data.Data_Transfer[0],S15STH.Read.Serial_Number.DATA[0],16)OTU(Port_Data.Port_Read.[Port])OTL(Local_Control.6);
   17: NOP();
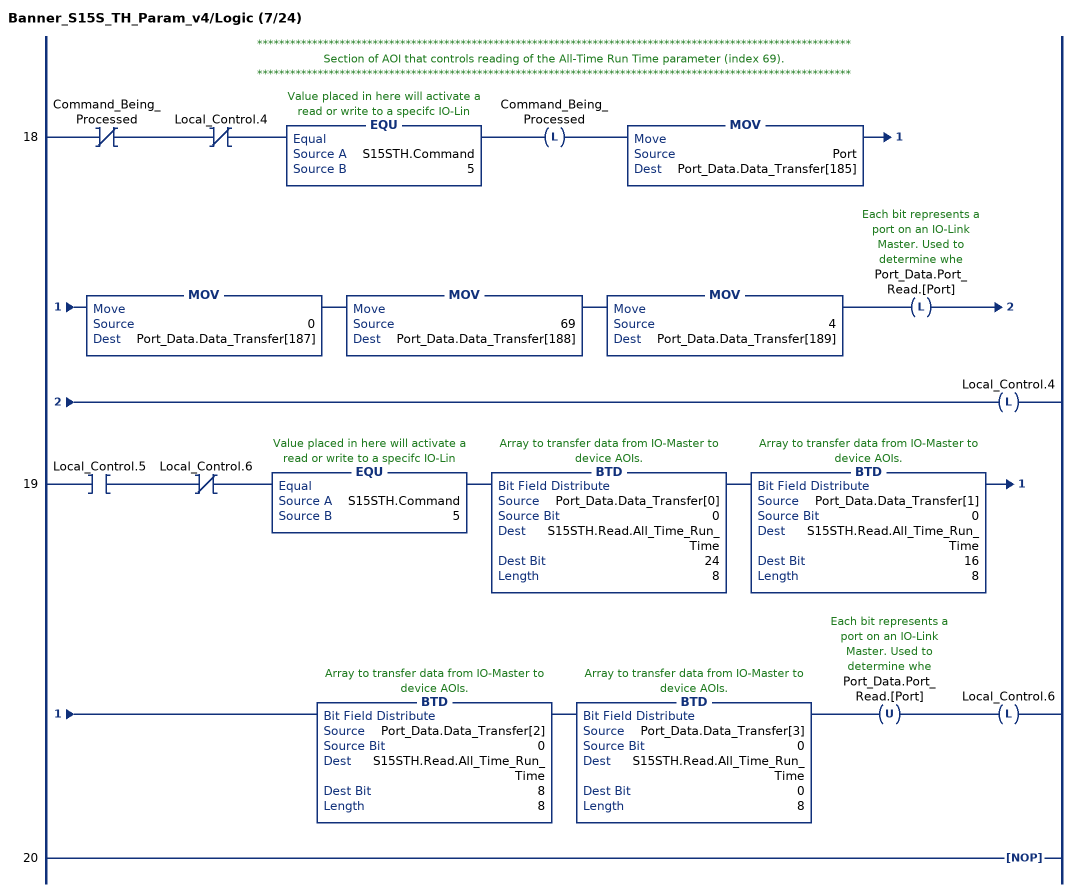
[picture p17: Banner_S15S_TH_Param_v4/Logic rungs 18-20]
   // ************************************************************************************************************
   // Section of AOI that controls reading of the All-Time Run Time parameter (index 69).
   // ************************************************************************************************************
   18: XIO(Command_Being_Processed)XIO(Local_Control.4)EQU(S15STH.Command,5)OTL(Command_Being_Processed)MOV(Port,Port_Data.Data_Transfer[185])MOV(0,Port_Data.Data_Transfer[187])MOV(69,Port_Data.Data_Transfer[188])MOV(4,Port_Data.Data_Transfer[189])OTL(Port_Data.Port_Read.[Port])OTL(Local_Control.4);
   19: XIC(Local_Control.5)XIO(Local_Control.6)EQU(S15STH.Command,5)BTD(Port_Data.Data_Transfer[0],0,S15STH.Read.All_Time_Run_Time,24,8)BTD(Port_Data.Data_Transfer[1],0,S15STH.Read.All_Time_Run_Time,16,8)BTD(Port_Data.Data_Transfer[2],0,S15STH.Read.All_Time_Run_Time,8,8)BTD(Port_Data.Data_Transfer[3],0,S15STH.Read.All_Time_Run_Time,0,8)OTU(Port_Data.Port_Read.[Port])OTL(Local_Control.6);
   20: NOP();
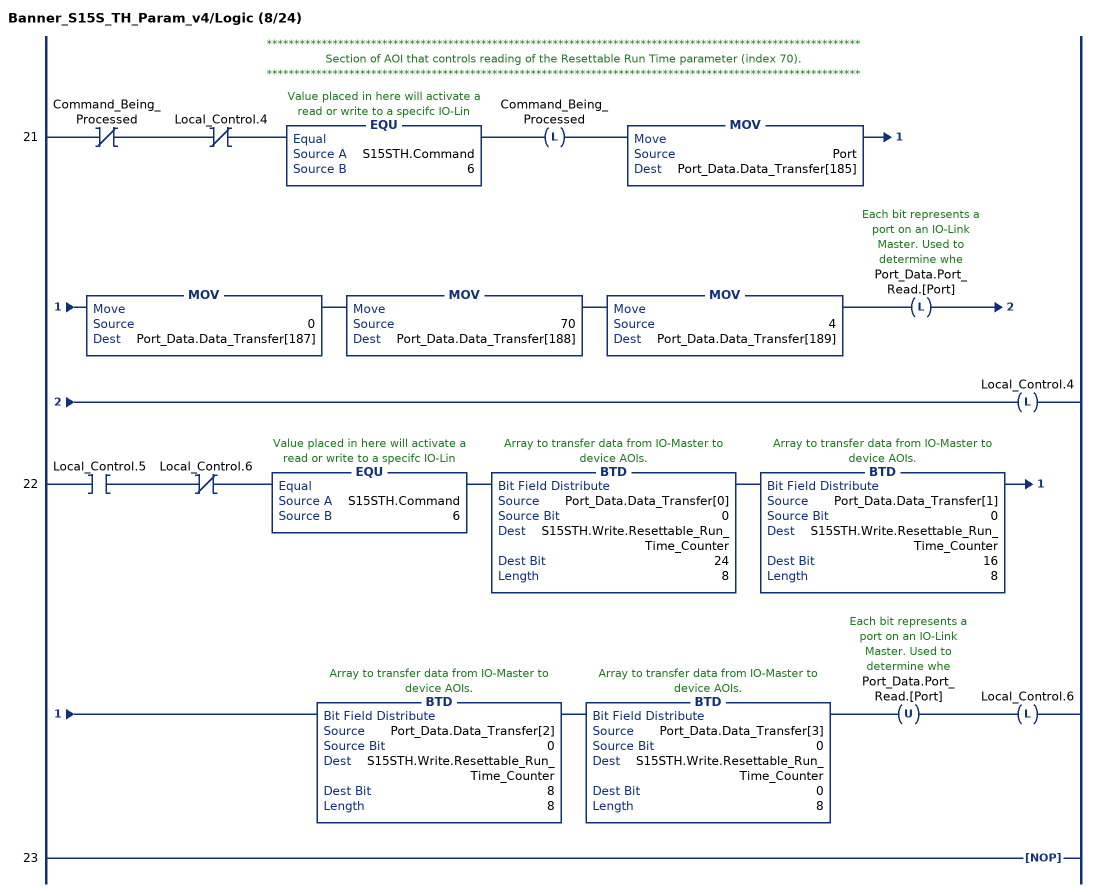
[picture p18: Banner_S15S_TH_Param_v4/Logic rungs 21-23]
   // ************************************************************************************************************
   // Section of AOI that controls reading of the Resettable Run Time parameter (index 70).
   // ************************************************************************************************************
   21: XIO(Command_Being_Processed)XIO(Local_Control.4)EQU(S15STH.Command,6)OTL(Command_Being_Processed)MOV(Port,Port_Data.Data_Transfer[185])MOV(0,Port_Data.Data_Transfer[187])MOV(70,Port_Data.Data_Transfer[188])MOV(4,Port_Data.Data_Transfer[189])OTL(Port_Data.Port_Read.[Port])OTL(Local_Control.4);
   22: XIC(Local_Control.5)XIO(Local_Control.6)EQU(S15STH.Command,6)BTD(Port_Data.Data_Transfer[0],0,S15STH.Write.Resettable_Run_Time_Counter,24,8)BTD(Port_Data.Data_Transfer[1],0,S15STH.Write.Resettable_Run_Time_Counter,16,8)BTD(Port_Data.Data_Transfer[2],0,S15STH.Write.Resettable_Run_Time_Counter,8,8)BTD(Port_Data.Data_Transfer[3],0,S15STH.Write.Resettable_Run_Time_Counter,0,8)OTU(Port_Data.Port_Read.[Port])OTL(Local_Control.6);
   23: NOP();
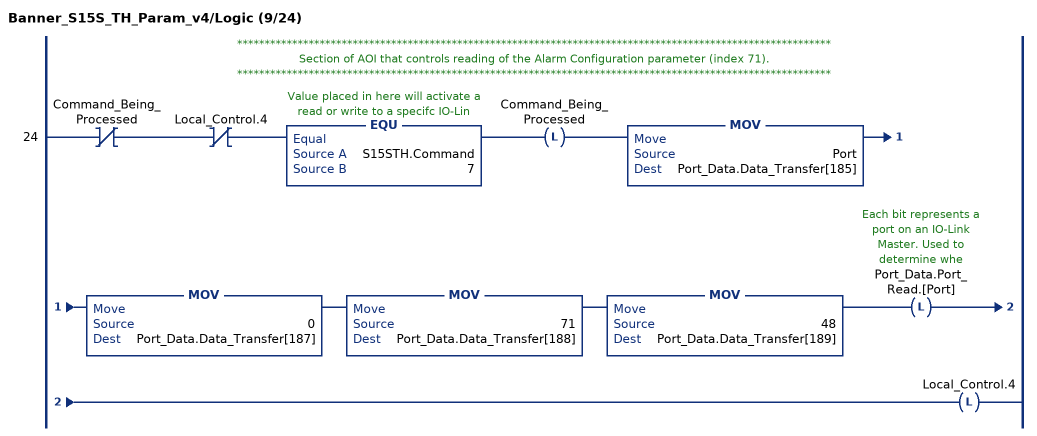
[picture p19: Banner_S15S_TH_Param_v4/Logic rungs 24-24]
   // ************************************************************************************************************
   // Section of AOI that controls reading of the Alarm Configuration parameter (index 71).
   // ************************************************************************************************************
   24: XIO(Command_Being_Processed)XIO(Local_Control.4)EQU(S15STH.Command,7)OTL(Command_Being_Processed)MOV(Port,Port_Data.Data_Transfer[185])MOV(0,Port_Data.Data_Transfer[187])MOV(71,Port_Data.Data_Transfer[188])MOV(48,Port_Data.Data_Transfer[189])OTL(Port_Data.Port_Read.[Port])OTL(Local_Control.4);
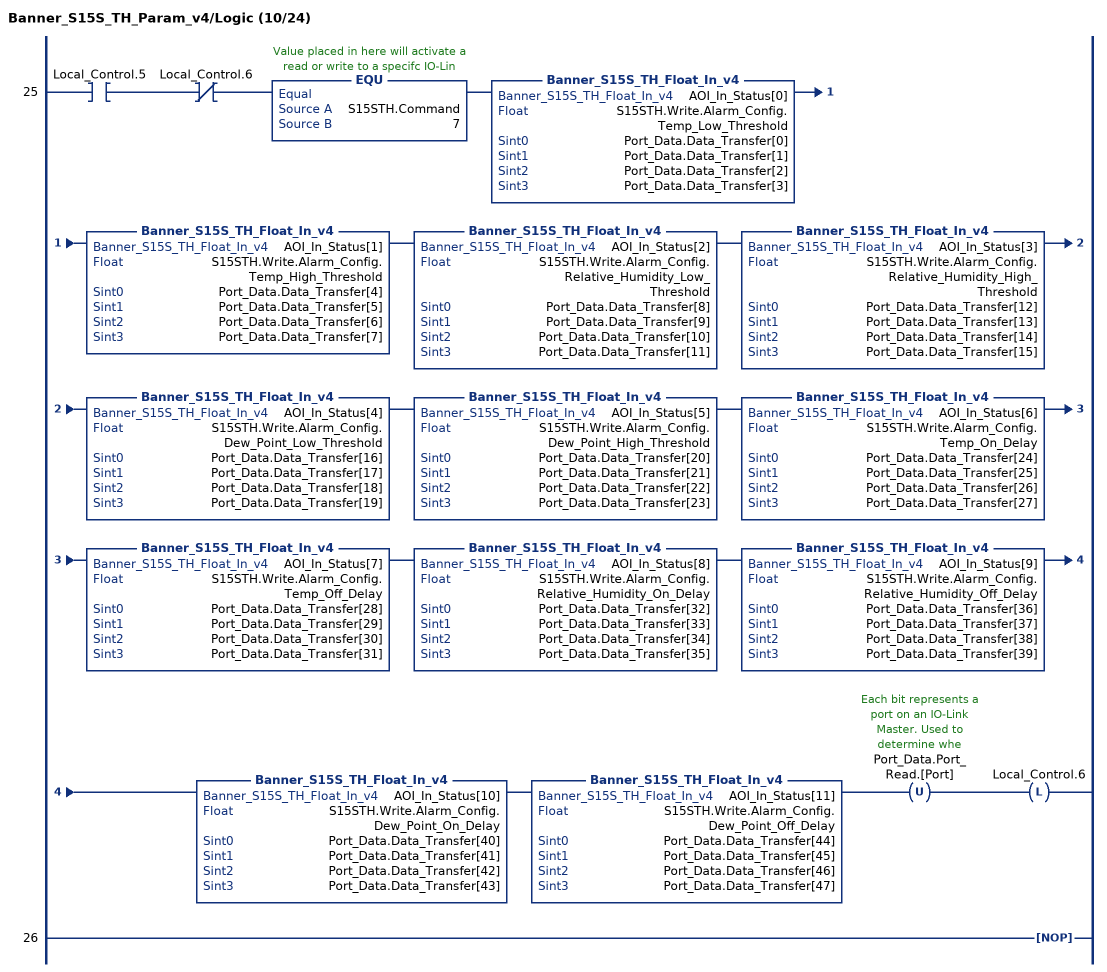
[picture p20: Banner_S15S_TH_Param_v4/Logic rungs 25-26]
   25: XIC(Local_Control.5)XIO(Local_Control.6)EQU(S15STH.Command,7)Banner_S15S_TH_Float_In_v4(AOI_In_Status[0],S15STH.Write.Alarm_Config.Temp_Low_Threshold,Port_Data.Data_Transfer[0],Port_Data.Data_Transfer[1],Port_Data.Data_Transfer[2],Port_Data.Data_Transfer[3])Banner_S15S_TH_Float_In_v4(AOI_In_Status[1],S15STH.Write.Alarm_Config.Temp_High_Threshold,Port_Data.Data_Transfer[4],Port_Data.Data_Transfer[5],Port_Data.Data_Transfer[6],Port_Data.Data_Transfer[7])Banner_S15S_TH_Float_In_v4(AOI_In_Status[2],S15STH.Write.Alarm_Config.Relative_Humidity_Low_Threshold,Port_Data.Data_Transfer[8],Port_Data.Data_Transfer[9],Port_Data.Data_Transfer[10],Port_Data.Data_Transfer[11])Banner_S15S_TH_Float_In_v4(AOI_In_Status[3],S15STH.Write.Alarm_Config.Relative_Humidity_High_Threshold,Port_Data.Data_Transfer[12],Port_Data.Data_Transfer[13],Port_Data.Data_Transfer[14],Port_Data.Data_Transfer[15])Banner_S15S_TH_Float_In_v4(AOI_In_Status[4],S15STH.Write.Alarm_Config.Dew_Point_Low_Threshold,Port_Data.Data_Transfer[16],Port_Data.Data_Transfer[17],Port_Data.Data_Transfer[18],Port_Data.Data_Transfer[19])Banner_S15S_TH_Float_In_v4(AOI_In_Status[5],S15STH.Write.Alarm_Config.Dew_Point_High_Threshold,Port_Data.Data_Transfer[20],Port_Data.Data_Transfer[21],Port_Data.Data_Transfer[22],Port_Data.Data_Transfer[23])Banner_S15S_TH_Float_In_v4(AOI_In_Status[6],S15STH.Write.Alarm_Config.Temp_On_Delay,Port_Data.Data_Transfer[24],Port_Data.Data_Transfer[25],Port_Data.Data_Transfer[26],Port_Data.Data_Transfer[27])Banner_S15S_TH_Float_In_v4(AOI_In_Status[7],S15STH.Write.Alarm_Config.Temp_Off_Delay,Port_Data.Data_Transfer[28],Port_Data.Data_Transfer[29],Port_Data.Data_Transfer[30],Port_Data.Data_Transfer[31])Banner_S15S_TH_Float_In_v4(AOI_In_Status[8],S15STH.Write.Alarm_Config.Relative_Humidity_On_Delay,Port_Data.Data_Transfer[32],Port_Data.Data_Transfer[33],Port_Data.Data_Transfer[34],Port_Data.Data_Transfer[35])Banner_S15S_TH_Float_In_v4(AOI_In_Status[9],S15STH.Write.Alarm_Config.Relative_Humidity_Off_Delay,Port_Data.Data_Transfer[36],Port_Data.Data_Transfer[37],Port_Data.Data_Transfer[38],Port_Data.Data_Transfer[39])Banner_S15S_TH_Float_In_v4(AOI_In_Status[10],S15STH.Write.Alarm_Config.Dew_Point_On_Delay,Port_Data.Data_Transfer[40],Port_Data.Data_Transfer[41],Port_Data.Data_Transfer[42],Port_Data.Data_Transfer[43])Banner_S15S_TH_Float_In_v4(AOI_In_Status[11],S15STH.Write.Alarm_Config.Dew_Point_Off_Delay,Port_Data.Data_Transfer[44],Port_Data.Data_Transfer[45],Port_Data.Data_Transfer[46],Port_Data.Data_Transfer[47])OTU(Port_Data.Port_Read.[Port])OTL(Local_Control.6);
   26: NOP();
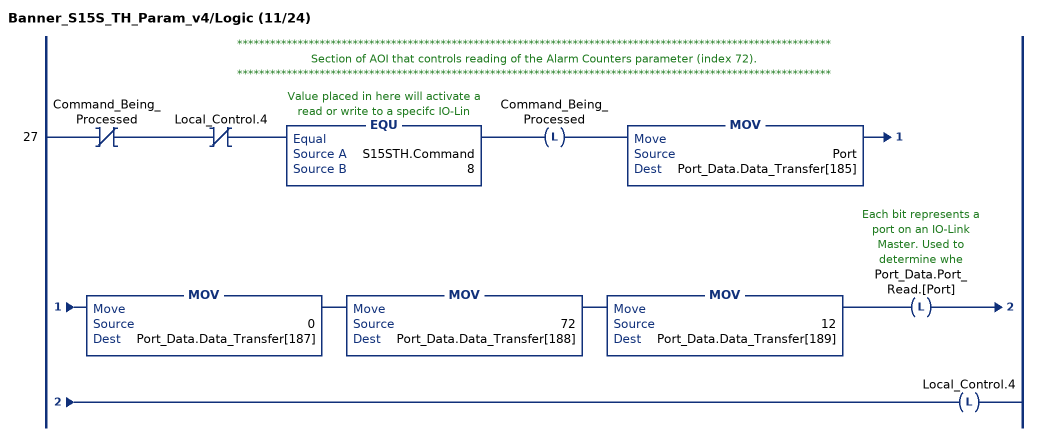
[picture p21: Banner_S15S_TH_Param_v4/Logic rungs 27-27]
   // ************************************************************************************************************
   // Section of AOI that controls reading of the Alarm Counters parameter (index 72).
   // ************************************************************************************************************
   27: XIO(Command_Being_Processed)XIO(Local_Control.4)EQU(S15STH.Command,8)OTL(Command_Being_Processed)MOV(Port,Port_Data.Data_Transfer[185])MOV(0,Port_Data.Data_Transfer[187])MOV(72,Port_Data.Data_Transfer[188])MOV(12,Port_Data.Data_Transfer[189])OTL(Port_Data.Port_Read.[Port])OTL(Local_Control.4);
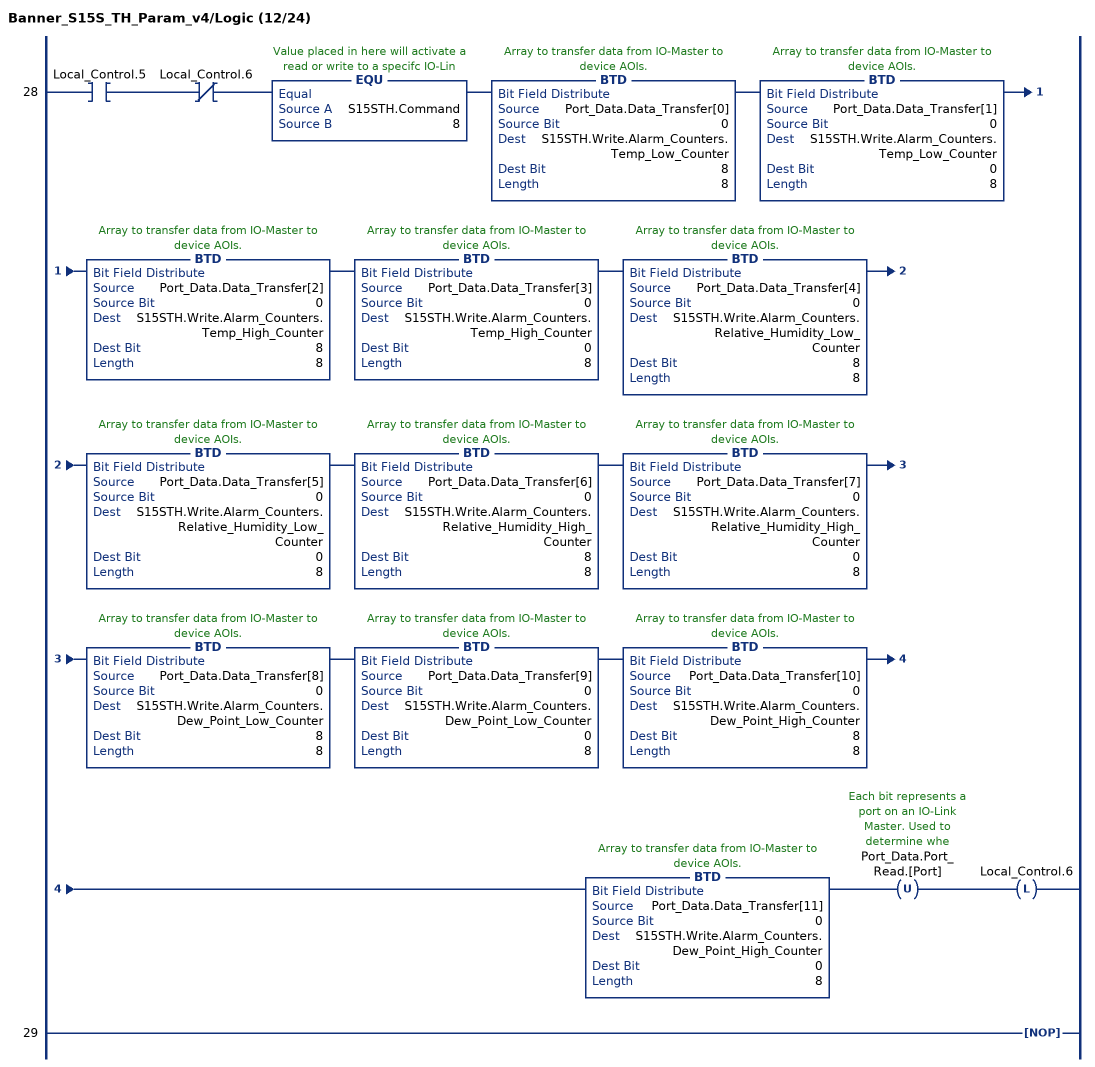
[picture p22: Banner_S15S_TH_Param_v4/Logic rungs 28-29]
   28: XIC(Local_Control.5)XIO(Local_Control.6)EQU(S15STH.Command,8)BTD(Port_Data.Data_Transfer[0],0,S15STH.Write.Alarm_Counters.Temp_Low_Counter,8,8)BTD(Port_Data.Data_Transfer[1],0,S15STH.Write.Alarm_Counters.Temp_Low_Counter,0,8)BTD(Port_Data.Data_Transfer[2],0,S15STH.Write.Alarm_Counters.Temp_High_Counter,8,8)BTD(Port_Data.Data_Transfer[3],0,S15STH.Write.Alarm_Counters.Temp_High_Counter,0,8)BTD(Port_Data.Data_Transfer[4],0,S15STH.Write.Alarm_Counters.Relative_Humidity_Low_Counter,8,8)BTD(Port_Data.Data_Transfer[5],0,S15STH.Write.Alarm_Counters.Relative_Humidity_Low_Counter,0,8)BTD(Port_Data.Data_Transfer[6],0,S15STH.Write.Alarm_Counters.Relative_Humidity_High_Counter,8,8)BTD(Port_Data.Data_Transfer[7],0,S15STH.Write.Alarm_Counters.Relative_Humidity_High_Counter,0,8)BTD(Port_Data.Data_Transfer[8],0,S15STH.Write.Alarm_Counters.Dew_Point_Low_Counter,8,8)BTD(Port_Data.Data_Transfer[9],0,S15STH.Write.Alarm_Counters.Dew_Point_Low_Counter,0,8)BTD(Port_Data.Data_Transfer[10],0,S15STH.Write.Alarm_Counters.Dew_Point_High_Counter,8,8)BTD(Port_Data.Data_Transfer[11],0,S15STH.Write.Alarm_Counters.Dew_Point_High_Counter,0,8)OTU(Port_Data.Port_Read.[Port])OTL(Local_Control.6);
   29: NOP();
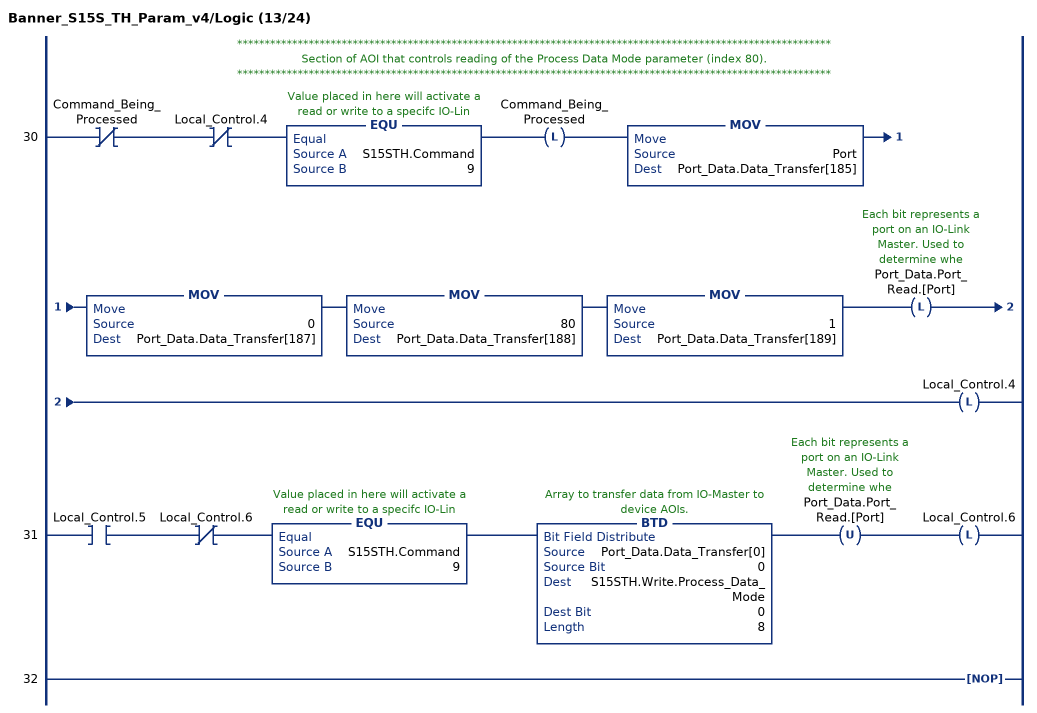
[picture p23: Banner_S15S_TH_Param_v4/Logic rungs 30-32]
   // ************************************************************************************************************
   // Section of AOI that controls reading of the Process Data Mode parameter (index 80).
   // ************************************************************************************************************
   30: XIO(Command_Being_Processed)XIO(Local_Control.4)EQU(S15STH.Command,9)OTL(Command_Being_Processed)MOV(Port,Port_Data.Data_Transfer[185])MOV(0,Port_Data.Data_Transfer[187])MOV(80,Port_Data.Data_Transfer[188])MOV(1,Port_Data.Data_Transfer[189])OTL(Port_Data.Port_Read.[Port])OTL(Local_Control.4);
   31: XIC(Local_Control.5)XIO(Local_Control.6)EQU(S15STH.Command,9)BTD(Port_Data.Data_Transfer[0],0,S15STH.Write.Process_Data_Mode,0,8)OTU(Port_Data.Port_Read.[Port])OTL(Local_Control.6);
   32: NOP();
